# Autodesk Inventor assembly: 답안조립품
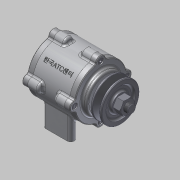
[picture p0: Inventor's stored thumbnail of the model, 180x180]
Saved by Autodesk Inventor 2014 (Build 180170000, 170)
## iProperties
Created: 2015-03
Part Number: 답안조립품
Document SubType Name: Assembly
Designer: Administrator
Author: Administrator
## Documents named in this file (11)
- C:\Documents and Settings\Administrator\바탕 화면\450306V1013\답안조립품.iam
- C:\Documents and Settings\Administrator\바탕 화면\450306V1013\본체.ipt
- C:\Documents and Settings\Administrator\바탕 화면\450306V1013\커버.ipt
- C:\Documents and Settings\Administrator\바탕 화면\450306V1013\M 4 x 12.ipt
- C:\Documents and Settings\Administrator\바탕 화면\450306V1013\오일실.ipt
- C:\Documents and Settings\Administrator\바탕 화면\450306V1013\커버2.ipt
- C:\Documents and Settings\Administrator\바탕 화면\450306V1013\축.ipt
- C:\Documents and Settings\Administrator\바탕 화면\450306V1013\베어링 6204.ipt
- C:\Documents and Settings\Administrator\바탕 화면\450306V1013\키(4 x 4 x 12).ipt
- C:\Documents and Settings\Administrator\바탕 화면\450306V1013\V벨트풀리.ipt
- C:\Documents and Settings\Administrator\바탕 화면\450306V1013\너트 M12x1.25.ipt
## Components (14 placed, 6 different names)
1. KS B 2804 D D - 20 32 8:1
2. KS B 2023 6204 - 20 x 47 x 14:1 — 각도:1
3. KS B 2023 6204 - 20 x 47 x 14:2 — 각도:2
4. KS B 1311 (I) 4 x 4 x 12:1
5. 그루브 풀리1:1
6. KS B 1012 클래스 1 일반 - 미터 M12x1.25:1 — 각도:3
7. KS B 1003 - 미터 M 4 x 12:1
8. KS B 1003 - 미터 M 4 x 12:2
9. KS B 1003 - 미터 M 4 x 12:3
10. KS B 1003 - 미터 M 4 x 12:4
11. KS B 1003 - 미터 M 4 x 12:5
12. KS B 1003 - 미터 M 4 x 12:6
13. KS B 1003 - 미터 M 4 x 12:7
14. KS B 1003 - 미터 M 4 x 12:8
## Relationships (3: Angle 3)
- 각도:1 [Angle]: KS B 2023 6204 - 20 x 47 x 14:1
- 각도:2 [Angle]: KS B 2023 6204 - 20 x 47 x 14:2
- 각도:3 [Angle]: KS B 1012 클래스 1 일반 - 미터 M12x1.25:1
